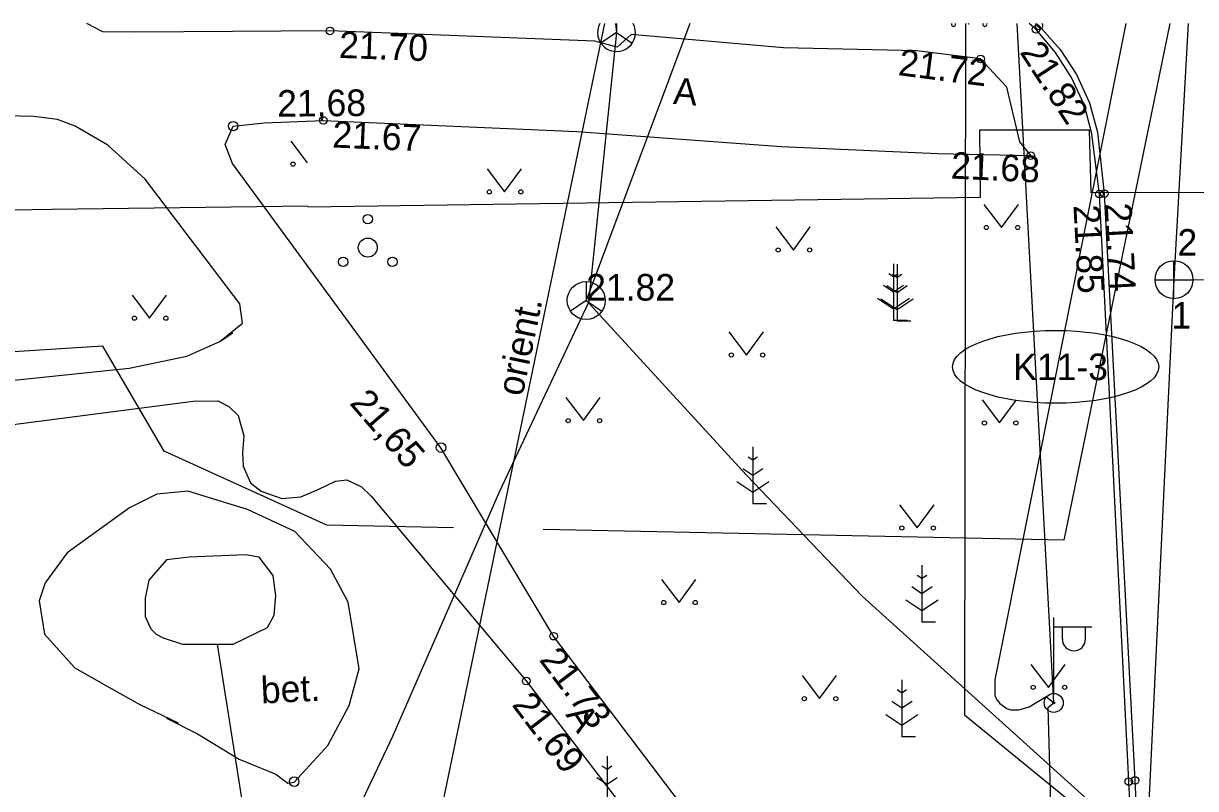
# Model space of a CAD drawing. Extents: x 714038 to 714279, y 6589845 to 6590041.
# Drawn here: x 714085.35 to 714116.25, y 6590020.81 to 6590040.97 of the extents above; entities that cross this region are included whole.
import ezdxf

# ---------------------------------------------------------------- set-up
doc = ezdxf.new("R2010")
doc.units = 0
for name, color, linetype in [('HALJASTUS', 7, 'Continuous'), ('KAEVU_NR', 7, 'Continuous'), ('KKAEV', 7, 'Continuous'), ('KORGUS', 7, 'Continuous'), ('KTRASS', 7, 'Continuous'), ('MPKAABEL', 7, 'Continuous'), ('POST', 7, 'Continuous'), ('PUU', 7, 'Continuous'), ('SIKAEV', 7, 'Continuous'), ('SITRASS', 7, 'Continuous'), ('SKTRASS', 7, 'Continuous'), ('TEE', 7, 'Continuous'), ('TORU NR', 7, 'Continuous'), ('TTRASS', 7, 'Continuous'), ('VEEKOGU', 7, 'Continuous'), ('VTRASS', 7, 'Continuous'), ('По умолчанию', 7, 'Continuous')]:
    doc.layers.add(name, color=color, linetype=linetype)

msp = doc.modelspace()

# ---------------------------------------------------------------- linework, layer by layer
at = {"layer": 'HALJASTUS'}
for p, q in [((714110.254, 6590040.965), (714110.269, 6590040.944)), ((714110.269, 6590040.944), (714110.285, 6590040.965)), ((714097.573, 6590037.135), (714098.036, 6590036.528)), ((714098.036, 6590036.528), (714098.482, 6590037.135)), ((714110.67, 6590036.196), (714111.133, 6590035.589)), ((714111.133, 6590035.589), (714111.579, 6590036.196)), ((714105.184, 6590035.603), (714105.648, 6590034.996)), ((714105.648, 6590034.996), (714106.093, 6590035.603)), ((714088.217, 6590033.807), (714088.68, 6590033.2)), ((714088.68, 6590033.2), (714089.126, 6590033.807)), ((714103.949, 6590032.837), (714104.412, 6590032.23)), ((714104.412, 6590032.23), (714104.858, 6590032.837)), ((714099.649, 6590031.107), (714100.112, 6590030.501)), ((714100.112, 6590030.501), (714100.558, 6590031.107)), ((714110.62, 6590031.047), (714111.084, 6590030.44)), ((714111.084, 6590030.44), (714111.529, 6590031.047)), ((714108.446, 6590028.281), (714108.909, 6590027.674)), ((714108.909, 6590027.674), (714109.355, 6590028.281)), ((714102.169, 6590026.315), (714102.633, 6590025.709)), ((714102.633, 6590025.709), (714103.078, 6590026.315)), ((714105.876, 6590023.785), (714106.339, 6590023.178)), ((714106.339, 6590023.178), (714106.785, 6590023.785)), ((714111.905, 6590024.081), (714112.369, 6590023.475)), ((714112.369, 6590023.475), (714112.814, 6590024.081))]:
    msp.add_line(p, q, dxfattribs=at)
for centre in [(714097.635, 6590036.528), (714098.464, 6590036.528), (714110.732, 6590035.589), (714111.561, 6590035.589), (714105.247, 6590034.996), (714106.075, 6590034.996), (714088.279, 6590033.2), (714089.108, 6590033.2), (714104.011, 6590032.23), (714104.84, 6590032.23), (714099.711, 6590030.501), (714100.54, 6590030.501), (714110.683, 6590030.44), (714111.512, 6590030.44), (714108.508, 6590027.674), (714109.337, 6590027.674), (714102.232, 6590025.709), (714103.06, 6590025.709), (714111.968, 6590023.475), (714112.797, 6590023.475), (714105.938, 6590023.178), (714106.767, 6590023.178)]:
    msp.add_circle(centre, 0.055, dxfattribs=at)
for centre in [(714109.868, 6590040.944), (714110.697, 6590040.944)]:
    msp.add_arc(centre, 0.055, 157.8406, 22.1594, dxfattribs=at)
at = {"layer": 'KAEVU_NR'}
msp.add_ellipse((714112.559, 6590031.918), major_axis=(2.717, 0), ratio=0.353371, dxfattribs=at)
at = {"layer": 'KKAEV'}
for p, q in [((714115.68, 6590033.714), (714115.68, 6590034.714)), ((714115.18, 6590034.214), (714116.18, 6590034.214))]:
    msp.add_line(p, q, dxfattribs=at)
msp.add_circle((714115.68, 6590034.214), 0.5, dxfattribs=at)
at = {"layer": 'KORGUS'}
for centre, radius in [((714093.43, 6590040.768), 0.1), ((714112.043, 6590040.807), 0.1), ((714110.583, 6590040.029), 0.1), ((714090.88, 6590038.26), 0.125), ((714093.257, 6590038.409), 0.1), ((714111.905, 6590037.484), 0.1), ((714113.715, 6590036.469), 0.1), ((714113.843, 6590036.482), 0.1), ((714096.36, 6590029.79), 0.125), ((714099.329, 6590024.823), 0.1), ((714098.608, 6590023.642), 0.1), ((714092.49, 6590020.99), 0.125), ((714114.489, 6590020.993), 0.1), ((714114.652, 6590021.023), 0.1)]:
    msp.add_circle(centre, radius, dxfattribs=at)
msp.add_arc((714112.122, 6590040.905), 0.1, 143.0902, 36.9098, dxfattribs=at)
at = {"layer": 'KTRASS'}
for points in [[(714116.057, 6590040.965), (714115.68, 6590034.214)], [(714115.68, 6590034.214), (714114.583, 6590011.444)], [(714115.68, 6590034.214), (714142.079, 6590034.235)]]:
    msp.add_lwpolyline(points, dxfattribs=at)
at = {"layer": 'MPKAABEL'}
for points in [[(714096.687, 6590027.681), (714093.35, 6590027.75), (714089.06, 6590029.7), (714087.45, 6590032.46), (714075.56, 6590031.71), (714050.79, 6590038.93), (714046.419, 6590040.965)], [(714115.568, 6590040.965), (714112.78, 6590027.35), (714099.056, 6590027.633)], [(714114.411, 6590040.965), (714110.96, 6590023.67), (714110.96, 6590023.53), (714110.96, 6590023.4), (714110.96, 6590023.25), (714111.02, 6590023.14), (714111.09, 6590023.05), (714111.27, 6590022.92), (714111.38, 6590022.88), (714111.59, 6590022.88), (714111.86, 6590022.96), (714112.31, 6590023.23), (714112.51, 6590023.065)], [(714112.51, 6590023.065), (714111.549, 6590040.965)], [(714113.38, 6589999.46), (714112.8, 6590009.74), (714112.51, 6590017.58), (714112.36, 6590022.95), (714112.51, 6590023.065)]]:
    msp.add_lwpolyline(points, dxfattribs=at)
at = {"layer": 'POST'}
for p, q in [((714112.51, 6590023.315), (714112.51, 6590025.315)), ((714112.51, 6590025.065), (714113.51, 6590025.065)), ((714112.737, 6590024.744), (714112.737, 6590025.065)), ((714113.349, 6590024.744), (714113.349, 6590025.065))]:
    msp.add_line(p, q, dxfattribs=at)
for radius in [0.25, 0.0234]:
    msp.add_circle((714112.51, 6590023.065), radius, dxfattribs=at)
msp.add_arc((714113.043, 6590024.744), 0.306, 180, 0, dxfattribs=at)
at = {"layer": 'PUU'}
for p, q in [((714108.287, 6590034.636), (714108.287, 6590033.136)), ((714108.38, 6590034.622), (714108.38, 6590033.122)), ((714108.287, 6590034.286), (714108.163, 6590034.369)), ((714108.38, 6590034.272), (714108.256, 6590034.355)), ((714108.411, 6590034.369), (714108.287, 6590034.286)), ((714108.504, 6590034.355), (714108.38, 6590034.272)), ((714108.287, 6590033.886), (714108.02, 6590034.064)), ((714108.38, 6590033.872), (714108.113, 6590034.05)), ((714108.554, 6590034.064), (714108.287, 6590033.886)), ((714108.647, 6590034.05), (714108.38, 6590033.872)), ((714107.863, 6590033.725), (714108.287, 6590033.443)), ((714107.956, 6590033.711), (714108.38, 6590033.429)), ((714108.287, 6590033.443), (714108.711, 6590033.725)), ((714108.38, 6590033.429), (714108.804, 6590033.711)), ((714108.647, 6590033.136), (714108.287, 6590033.136)), ((714108.74, 6590033.122), (714108.38, 6590033.122)), ((714104.578, 6590029.807), (714104.578, 6590028.307)), ((714104.578, 6590029.457), (714104.454, 6590029.54)), ((714104.702, 6590029.54), (714104.578, 6590029.457)), ((714104.578, 6590029.057), (714104.311, 6590029.235)), ((714104.845, 6590029.235), (714104.578, 6590029.057)), ((714104.154, 6590028.896), (714104.578, 6590028.614)), ((714104.578, 6590028.614), (714105.002, 6590028.896)), ((714104.938, 6590028.307), (714104.578, 6590028.307)), ((714109.037, 6590026.691), (714109.037, 6590025.191)), ((714109.037, 6590026.341), (714108.913, 6590026.424)), ((714109.161, 6590026.424), (714109.037, 6590026.341)), ((714109.037, 6590025.941), (714108.77, 6590026.119)), ((714109.304, 6590026.119), (714109.037, 6590025.941)), ((714108.613, 6590025.78), (714109.037, 6590025.498)), ((714109.037, 6590025.498), (714109.461, 6590025.78)), ((714109.397, 6590025.191), (714109.037, 6590025.191)), ((714108.508, 6590023.672), (714108.508, 6590022.172)), ((714108.508, 6590023.322), (714108.384, 6590023.405)), ((714108.632, 6590023.405), (714108.508, 6590023.322)), ((714108.508, 6590022.922), (714108.241, 6590023.1)), ((714108.775, 6590023.1), (714108.508, 6590022.922)), ((714108.084, 6590022.761), (714108.508, 6590022.479)), ((714108.508, 6590022.479), (714108.932, 6590022.761)), ((714108.868, 6590022.172), (714108.508, 6590022.172)), ((714100.735, 6590021.663), (714100.735, 6590020.163)), ((714100.735, 6590021.313), (714100.611, 6590021.396)), ((714100.859, 6590021.396), (714100.735, 6590021.313)), ((714100.735, 6590020.913), (714100.468, 6590021.091)), ((714101.002, 6590021.091), (714100.735, 6590020.913))]:
    msp.add_line(p, q, dxfattribs=at)
for centre, radius in [((714094.429, 6590035.81), 0.125), ((714094.429, 6590035.06), 0.25), ((714093.779, 6590034.685), 0.125), ((714095.079, 6590034.685), 0.125)]:
    msp.add_circle(centre, radius, dxfattribs=at)
at = {"layer": 'SIKAEV'}
for p, q in [((714100.987, 6590040.965), (714100.987, 6590040.724)), ((714100.987, 6590040.724), (714100.572, 6590040.449)), ((714100.987, 6590040.724), (714101.402, 6590040.449)), ((714100.187, 6590034.164), (714100.187, 6590033.664)), ((714100.187, 6590033.664), (714099.772, 6590033.389)), ((714100.187, 6590033.664), (714100.602, 6590033.389))]:
    msp.add_line(p, q, dxfattribs=at)
msp.add_circle((714100.187, 6590033.664), 0.5, dxfattribs=at)
msp.add_arc((714100.987, 6590040.724), 0.5, 151.1766, 28.8234, dxfattribs=at)
at = {"layer": 'SITRASS'}
for points in [[(714102.919, 6590040.965), (714100.187, 6590033.664)], [(714100.963, 6590040.965), (714100.987, 6590040.724), (714100.251, 6590033.606)], [(714078.609, 6589985.937), (714086.299, 6590002.484), (714089.168, 6590008.661), (714094.05, 6590020), (714095.092, 6590022.185), (714097.899, 6590028.624), (714100.251, 6590033.606)], [(714119.667, 6590015.291), (714118.134, 6590016.633), (714114.596, 6590019.438), (714107.457, 6590025.877), (714104.409, 6590029.065), (714100.251, 6590033.606)]]:
    msp.add_lwpolyline(points, dxfattribs=at)
at = {"layer": 'SKTRASS'}
for points in [[(714093.717, 6590007.479), (714100.679, 6590040.965)], [(714092.643, 6590010.832), (714090.47, 6590024.61)]]:
    msp.add_lwpolyline(points, dxfattribs=at)
at = {"layer": 'TEE'}
for points in [[(714103.95, 6590018.741), (714099.329, 6590024.823), (714096.359, 6590029.789), (714090.86, 6590037.277), (714090.668, 6590037.777), (714090.881, 6590038.261), (714091.696, 6590038.349), (714093.257, 6590038.409), (714099.938, 6590038.117), (714105.332, 6590037.725), (714109.449, 6590037.535), (714111.905, 6590037.484), (714111.62, 6590037.847), (714111.275, 6590039.287), (714110.583, 6590040.029), (714108.903, 6590040.245), (714105.388, 6590040.321), (714101.372, 6590040.678), (714101.001, 6590040.336), (714100.413, 6590040.501), (714093.43, 6590040.768), (714088.294, 6590040.738), (714087.443, 6590040.743), (714087.023, 6590040.965)], [(714112.613, 6589994.344), (714115.842, 6589994.528), (714115.19, 6590007.83), (714114.489, 6590020.993), (714113.715, 6590036.469), (714113.516, 6590038.053), (714113.32, 6590038.801), (714112.982, 6590039.544), (714112.557, 6590040.196), (714112.043, 6590040.807), (714111.861, 6590040.965)], [(714112.052, 6590040.965), (714112.122, 6590040.905), (714112.679, 6590040.278), (714113.106, 6590039.617), (714113.451, 6590038.877), (714113.663, 6590038.097), (714113.843, 6590036.482), (714114.652, 6590021.023), (714115.306, 6590007.823), (714116.037, 6589994.37), (714112.851, 6589994.202)], [(714061.418, 6590031.365), (714064.028, 6590029.649), (714065.041, 6590029.48), (714088.138, 6590031.885), (714089.66, 6590032.196), (714090.532, 6590032.585), (714091.13, 6590033.07), (714091.054, 6590033.578), (714088.562, 6590036.861), (714087.579, 6590037.76), (714086.716, 6590038.263), (714086.251, 6590038.431), (714085.627, 6590038.511), (714084.494, 6590038.541), (714077.674, 6590037.967), (714070.836, 6590036.585), (714063.955, 6590034.984), (714059.67, 6590033.631), (714059.535, 6590033.112), (714060.214, 6590032.388), (714061.418, 6590031.365)], [(714086.716, 6590038.263), (714086.251, 6590038.431)], [(714090.86, 6590037.277), (714090.668, 6590037.777)], [(714090.532, 6590032.585), (714090.872, 6590032.816)], [(714056.537, 6590027.513), (714056.966, 6590027.804), (714057.559, 6590027.491), (714057.807, 6590027.264), (714058.362, 6590027.017), (714058.907, 6590027.007), (714089.829, 6590031.012), (714090.473, 6590031.023), (714090.766, 6590030.875), (714091.01, 6590030.635), (714091.159, 6590030.105), (714091.125, 6590029.656), (714091.141, 6590029.299), (714091.34, 6590028.86), (714091.618, 6590028.64), (714092.164, 6590028.45), (714092.663, 6590028.49), (714093.12, 6590028.689), (714093.575, 6590028.907), (714093.878, 6590028.938), (714094.262, 6590028.758), (714094.522, 6590028.514), (714098.608, 6590023.642)], [(714091.141, 6590029.299), (714091.34, 6590028.86)], [(714094.262, 6590028.758), (714094.522, 6590028.514)], [(714089.12, 6590022.66), (714089.94, 6590022.25), (714091.04, 6590021.58), (714092.01, 6590021.19), (714092.32, 6590020.95), (714092.49, 6590020.98), (714092.8, 6590021.31), (714093.38, 6590021.94), (714093.94, 6590023), (714094.2, 6590023.96), (714093.91, 6590025.72), (714093.45, 6590026.59), (714092.51, 6590027.58), (714091.26, 6590028.16), (714089.69, 6590028.64), (714088.87, 6590028.56), (714088.15, 6590028.2), (714086.51, 6590027.02), (714085.93, 6590026.23), (714085.77, 6590025.75), (714085.91, 6590024.88), (714086.71, 6590023.99), (714087.6, 6590023.48), (714088.42, 6590023.02), (714089.43, 6590022.54)], [(714098.608, 6590023.642), (714103.037, 6590017.849)]]:
    msp.add_lwpolyline(points, dxfattribs=at)
at = {"layer": 'TTRASS'}
for points in [[(714092.848, 6590036.148), (714086.1, 6590036.06), (714063.31, 6590035.69), (714063.31, 6590037.93), (714060.79, 6590037.93), (714060.74, 6590035.6), (714051.43, 6590035.57), (714040.343, 6590040.965)], [(714132.293, 6590036.559), (714113.5, 6590036.5), (714113.45, 6590038.15), (714110.55, 6590038.15), (714110.573, 6590036.38), (714092.848, 6590036.126)]]:
    msp.add_lwpolyline(points, dxfattribs=at)
at = {"layer": 'VEEKOGU'}
msp.add_lwpolyline([(714090.88, 6590024.61), (714091.79, 6590025.05), (714091.96, 6590025.38), (714092.01, 6590025.89), (714091.94, 6590026.42), (714091.57, 6590026.9), (714091.21, 6590026.97), (714089.72, 6590026.9), (714089.12, 6590026.83), (714088.66, 6590026.3), (714088.56, 6590025.82), (714088.56, 6590025.34), (714088.71, 6590025.02), (714088.85, 6590024.88), (714089.04, 6590024.78), (714089.55, 6590024.61), (714090.88, 6590024.61)], dxfattribs=at)
at = {"layer": 'VTRASS'}
msp.add_lwpolyline([(714110.18, 6590040.965), (714110.16, 6590022.75), (714121.63, 6590013.38), (714123.019, 6590013.414)], dxfattribs=at)
at = {"layer": 'По умолчанию'}
msp.add_line((714092.397, 6590037.867), (714092.833, 6590037.295), dxfattribs=at)
msp.add_circle((714092.459, 6590037.26), 0.055, dxfattribs=at)

# ---------------------------------------------------------------- texts
at = {"layer": 'KAEVU_NR'}
msp.add_text('K11-3', height=0.7, dxfattribs=at).set_placement((714111.441, 6590031.568))
at = {"layer": 'KORGUS'}
for s, rotation, p in [(' 21.70', 357.8103, (714093.403, 6590040.069)), (' 21.82', 303.0979, (714111.457, 6590040.425)), (' 21.72', 352.6736, (714108.133, 6590039.638)), ('21,68', 0.4863, (714092.044, 6590038.508)), (' 21.67', 357.4974, (714093.226, 6590037.71)), (' 21.68', 357.3577, (714109.53, 6590036.893)), (' 21.85', 272.9957, (714113.016, 6590036.432)), (' 21.74', 272.9957, (714113.843, 6590036.482)), ('21,65', 310.9666, (714093.929, 6590030.951)), (' 21.73', 307.227, (714098.772, 6590024.4)), (' 21.69', 307.227, (714098.051, 6590023.219))]:
    msp.add_text(s, height=0.7, rotation=rotation, dxfattribs=at).set_placement(p)
msp.add_text('21.82', height=0.7, dxfattribs=at).set_placement((714100.187, 6590033.664))
at = {"layer": 'SKTRASS'}
msp.add_text('orient.', height=0.7, rotation=78.2557, dxfattribs=at).set_placement((714098.507, 6590031.118))
at = {"layer": 'TEE'}
for s, rotation, p in [('A', 355.8434, (714102.465, 6590038.845)), ('bet.', 2.7396, (714091.627, 6590023.048)), ('A', 303.2576, (714099.629, 6590022.754))]:
    msp.add_text(s, height=0.7, rotation=rotation, dxfattribs=at).set_placement(p)
at = {"layer": 'TORU NR'}
for s, p in [('2', (714115.772, 6590034.847)), ('1', (714115.613, 6590032.925))]:
    msp.add_text(s, height=0.7, dxfattribs=at).set_placement(p)

doc.saveas('drawing.dxf')
